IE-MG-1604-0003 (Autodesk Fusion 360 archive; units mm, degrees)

design "IS-MG-1604-0004" references "LED", "SFP SLOT", "Pluggable Terminal Block", "USB Type C Port (SMD Type) (1)", "Digitus_DN-651107_LAN-Switch x2", "8 ports ethernet", "M2.4 Screw", "DIP Switch"
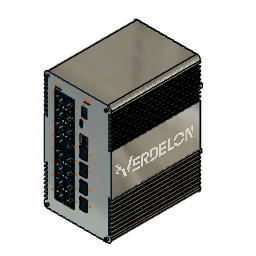
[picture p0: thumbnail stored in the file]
sketch "Sketch1" plane through (0, 0, 0) normal (0, 1, 0) x axis (1, 0, 0)
  line L1 (85, 0) -> (5, 0)
  line L2 (90, -155) -> (90, -5)
  line L3 (5, -160) -> (85, -160)
  line L4 (0, -5) -> (0, -155)
  arc A1 centre (85, -5) radius 5 clockwise from (85, 0) to (90, -5)
  arc A2 centre (5, -5) radius 5 clockwise from (0, -5) to (5, 0)
  arc A3 centre (85, -155) radius 5 clockwise from (90, -155) to (85, -160)
  arc A4 centre (5, -155) radius 5 clockwise from (5, -160) to (0, -155)
  point P1 (0, 0)
  point P2 (0, 0)
  point P3 (90, 0)
  point P4 (0, -160)
  horizontal L1
  vertical L2
  horizontal L3
  vertical L4
  coincident P1 P2
  coincident P3 L1
  coincident P3 L2
  tangent L1 A1
  tangent L2 A1
  coincident P2 L1
  coincident P2 L4
  tangent L1 A2
  tangent L4 A2
  equal A1 A2
  tangent L2 A3
  tangent L3 A3
  equal A1 A3
  coincident P4 L3
  coincident P4 L4
  tangent L3 A4
  tangent L4 A4
  equal A1 A4
  dimension "d1" distance P2 P4 = 160
  dimension "d2" distance P2 P3 = 90
  dimension "d3" radius A1 = 5
extrude "Extrude1" new body sketch "Sketch1" along normal blind 120
sketch "Sketch2" plane through (0, 0, 0) normal (0, -1, 0) x axis (1, 0, 0)
  line L1 (85, 0) -> (5, 0)
  line L2 (90, 155) -> (90, 5)
  line L3 (5, 160) -> (85, 160)
  line L4 (45, 80) -> (45, 160)
  line L5 (45, 80) -> (0, 80)
  line L6 (3.4641, 53) -> (0, 51)
  line L7 (3.4641, 50) -> (0, 48)
  line L8 (3.4641, 53) -> (3.4641, 50)
  line L9 (0, 51) -> (0, 48)
  line L10 (3.4641, 45) -> (0, 43)
  line L11 (0, 46) -> (0, 43)
  line L12 (3.4641, 48) -> (3.4641, 45)
  line L13 (3.4641, 48) -> (0, 46)
  line L14 (3.4641, 40) -> (0, 38)
  line L15 (0, 41) -> (0, 38)
  line L16 (3.4641, 43) -> (3.4641, 40)
  line L17 (3.4641, 43) -> (0, 41)
  line L18 (3.4641, 35) -> (0, 33)
  line L19 (0, 36) -> (0, 33)
  line L20 (3.4641, 38) -> (3.4641, 35)
  line L21 (3.4641, 38) -> (0, 36)
  line L22 (3.4641, 30) -> (0, 28)
  line L23 (0, 31) -> (0, 28)
  line L24 (3.4641, 33) -> (3.4641, 30)
  line L25 (3.4641, 33) -> (0, 31)
  line L26 (3.4641, 25) -> (0, 23)
  line L27 (0, 26) -> (0, 23)
  line L28 (3.4641, 28) -> (3.4641, 25)
  line L29 (3.4641, 28) -> (0, 26)
  line L30 (3.4641, 20) -> (0, 18)
  line L31 (0, 21) -> (0, 18)
  line L32 (3.4641, 23) -> (3.4641, 20)
  line L33 (3.4641, 23) -> (0, 21)
  line L34 (3.4641, 15) -> (0, 13)
  line L35 (0, 16) -> (0, 13)
  line L36 (3.4641, 18) -> (3.4641, 15)
  line L37 (3.4641, 18) -> (0, 16)
  line L38 (3.4641, 10) -> (0, 8)
  line L39 (0, 11) -> (0, 8)
  line L40 (3.4641, 13) -> (3.4641, 10)
  line L41 (3.4641, 13) -> (0, 11)
  line L42 (0, 129) -> (0, 132)
  line L43 (0, 149) -> (0, 152)
  line L44 (0, 109) -> (0, 112)
  line L45 (3.4641, 115) -> (0, 117)
  line L46 (3.4641, 112) -> (0, 114)
  line L47 (0, 119) -> (0, 122)
  line L48 (3.4641, 137) -> (3.4641, 140)
  line L49 (3.4641, 150) -> (0, 152)
  line L50 (3.4641, 142) -> (0, 144)
  line L51 (3.4641, 127) -> (0, 129)
  line L52 (0, 114) -> (0, 117)
  line L53 (3.4641, 122) -> (3.4641, 125)
  line L54 (3.4641, 142) -> (3.4641, 145)
  line L55 (3.4641, 135) -> (0, 137)
  line L56 (3.4641, 110) -> (0, 112)
  line L57 (3.4641, 132) -> (0, 134)
  line L58 (3.4641, 117) -> (0, 119)
  line L59 (0, 134) -> (0, 137)
  line L60 (3.4641, 117) -> (3.4641, 120)
  line L61 (3.4641, 130) -> (0, 132)
  line L62 (0, 144) -> (0, 147)
  line L63 (3.4641, 147) -> (0, 149)
  line L64 (3.4641, 147) -> (3.4641, 150)
  line L65 (3.4641, 122) -> (0, 124)
  line L66 (0, 124) -> (0, 127)
  line L67 (3.4641, 125) -> (0, 127)
  line L68 (3.4641, 107) -> (0, 109)
  line L69 (3.4641, 107) -> (3.4641, 110)
  line L70 (3.4641, 140) -> (0, 142)
  line L71 (3.4641, 145) -> (0, 147)
  line L72 (3.4641, 112) -> (3.4641, 115)
  line L73 (3.4641, 137) -> (0, 139)
  line L74 (0, 139) -> (0, 142)
  line L75 (3.4641, 132) -> (3.4641, 135)
  line L76 (3.4641, 120) -> (0, 122)
  line L77 (3.4641, 127) -> (3.4641, 130)
  line L78 (86.5359, 135) -> (90, 137)
  line L79 (90, 144) -> (90, 147)
  line L80 (90, 149) -> (90, 152)
  line L81 (90, 124) -> (90, 127)
  line L82 (86.5359, 120) -> (90, 122)
  line L83 (86.5359, 107) -> (90, 109)
  line L84 (86.5359, 117) -> (90, 119)
  line L85 (86.5359, 137) -> (90, 139)
  line L86 (86.5359, 122) -> (90, 124)
  line L87 (86.5359, 117) -> (86.5359, 120)
  line L88 (90, 114) -> (90, 117)
  line L89 (86.5359, 127) -> (86.5359, 130)
  line L90 (86.5359, 115) -> (90, 117)
  line L91 (86.5359, 130) -> (90, 132)
  line L92 (86.5359, 147) -> (86.5359, 150)
  line L93 (86.5359, 142) -> (86.5359, 145)
  line L94 (86.5359, 142) -> (90, 144)
  line L95 (90, 109) -> (90, 112)
  line L96 (90, 134) -> (90, 137)
  line L97 (86.5359, 107) -> (86.5359, 110)
  line L98 (86.5359, 132) -> (86.5359, 135)
  line L99 (86.5359, 112) -> (86.5359, 115)
  line L100 (86.5359, 137) -> (86.5359, 140)
  line L101 (86.5359, 110) -> (90, 112)
  line L102 (86.5359, 132) -> (90, 134)
  line L103 (86.5359, 145) -> (90, 147)
  line L104 (86.5359, 150) -> (90, 152)
  line L105 (90, 129) -> (90, 132)
  line L106 (86.5359, 112) -> (90, 114)
  line L107 (86.5359, 147) -> (90, 149)
  line L108 (90, 119) -> (90, 122)
  line L109 (86.5359, 127) -> (90, 129)
  line L110 (86.5359, 125) -> (90, 127)
  line L111 (86.5359, 122) -> (86.5359, 125)
  line L112 (90, 139) -> (90, 142)
  line L113 (86.5359, 140) -> (90, 142)
  line L114 (86.5359, 48) -> (86.5359, 45)
  line L115 (90, 46) -> (90, 43)
  line L116 (90, 36) -> (90, 33)
  line L117 (90, 41) -> (90, 38)
  line L118 (86.5359, 15) -> (90, 13)
  line L119 (90, 21) -> (90, 18)
  line L120 (86.5359, 53) -> (90, 51)
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  point P14 (45, 160)
  point P17 (0, 51)
  point P56 (0, 109)
  point P18 (3.4641, 53)
  point P88 (3.4641, 107)
  point P19 (0, 48)
  point P54 (0, 112)
  point P20 (3.4641, 50)
  point P55 (3.4641, 110)
  point P21 (0, 43)
  point P62 (0, 117)
  point P22 (3.4641, 45)
  point P61 (3.4641, 115)
  point P23 (0, 46)
  point P59 (0, 114)
  point P24 (3.4641, 48)
  point P60 (3.4641, 112)
  point P25 (0, 38)
  point P58 (0, 122)
  point P26 (3.4641, 40)
  point P53 (3.4641, 120)
  point P27 (0, 41)
  point P57 (0, 119)
  point P28 (3.4641, 43)
  point P85 (3.4641, 117)
  point P29 (0, 33)
  point P81 (0, 127)
  point P30 (3.4641, 35)
  point P78 (3.4641, 125)
  point P31 (0, 36)
  point P80 (0, 124)
  point P32 (3.4641, 38)
  point P86 (3.4641, 122)
  point P33 (0, 28)
  point P79 (0, 132)
  point P34 (3.4641, 30)
  point P87 (3.4641, 130)
  point P35 (0, 31)
  point P82 (0, 129)
  point P36 (3.4641, 33)
  point P75 (3.4641, 127)
  point P37 (0, 23)
  point P83 (0, 137)
  point P38 (3.4641, 25)
  point P77 (3.4641, 135)
  point P39 (0, 26)
  point P84 (0, 134)
  point P40 (3.4641, 28)
  point P76 (3.4641, 132)
  point P41 (0, 18)
  point P70 (0, 142)
  point P42 (3.4641, 20)
  point P68 (3.4641, 140)
  point P43 (0, 21)
  point P74 (0, 139)
  point P44 (3.4641, 23)
  point P71 (3.4641, 137)
  point P45 (0, 13)
  point P63 (0, 147)
  point P46 (3.4641, 15)
  point P67 (3.4641, 145)
  point P47 (0, 16)
  point P73 (0, 144)
  point P48 (3.4641, 18)
  point P65 (3.4641, 142)
  point P49 (0, 8)
  point P69 (0, 152)
  point P50 (3.4641, 10)
  point P64 (3.4641, 150)
  point P51 (0, 11)
  point P66 (0, 149)
  point P52 (3.4641, 13)
  point P72 (3.4641, 147)
  point P11 (5, 160)
  point P163 (85, 160)
  point P12 (0, 155)
  point P120 (90, 155)
  point P127 (90, 51)
  point P130 (86.5359, 53)
  point P128 (90, 48)
  point P140 (86.5359, 50)
  point P132 (90, 43)
  point P159 (86.5359, 45)
  point P153 (90, 46)
  point P150 (86.5359, 48)
  point P152 (90, 38)
  point P146 (86.5359, 40)
  point P135 (90, 41)
  point P138 (86.5359, 43)
  point P133 (90, 33)
  point P134 (86.5359, 35)
  point P129 (90, 36)
  point P131 (86.5359, 38)
  point P143 (90, 28)
  point P144 (86.5359, 30)
  point P142 (90, 31)
  point P147 (86.5359, 33)
  point P149 (90, 23)
  point P160 (86.5359, 25)
  point P162 (90, 26)
  point P161 (86.5359, 28)
  point P155 (90, 18)
  point P148 (86.5359, 20)
  point P154 (90, 21)
  point P151 (86.5359, 23)
  point P145 (90, 13)
  point P141 (86.5359, 15)
  point P157 (90, 16)
  point P156 (86.5359, 18)
  point P158 (90, 8)
  point P136 (86.5359, 10)
  point P137 (90, 11)
  point P139 (86.5359, 13)
  point P91 (86.5359, 120)
  point P93 (90, 112)
  point P119 (86.5359, 110)
  point P115 (90, 109)
  point P116 (90, 119)
  point P118 (90, 122)
  point P123 (90, 114)
  point P108 (86.5359, 112)
  point P97 (86.5359, 115)
  point P110 (90, 117)
  point P99 (90, 147)
  point P111 (86.5359, 150)
  point P104 (86.5359, 142)
  point P105 (90, 149)
  point P101 (86.5359, 145)
  point P103 (86.5359, 140)
  point P95 (90, 152)
  point P98 (90, 142)
  point P96 (86.5359, 137)
  point P100 (86.5359, 147)
  point P117 (90, 144)
  point P126 (90, 139)
  point P106 (86.5359, 127)
  point P107 (86.5359, 132)
  point P114 (86.5359, 135)
  point P102 (86.5359, 125)
  point P121 (90, 132)
  point P113 (90, 124)
  point P124 (90, 127)
  point P112 (90, 129)
  point P125 (90, 137)
  point P89 (90, 134)
  point P122 (86.5359, 117)
  point P94 (86.5359, 122)
  point P90 (86.5359, 130)
  point P92 (86.5359, 107)
  midpoint L3 P14
  perpendicular L3 L4
  perpendicular L4 L5
  symmetric L5 P17 P56
  symmetric L5 P18 P88
  symmetric L5 P19 P54
  symmetric L5 P20 P55
  symmetric L5 P21 P62
  symmetric L5 P22 P61
  symmetric L5 P23 P59
  symmetric L5 P24 P60
  symmetric L5 P25 P58
  symmetric L5 P26 P53
  symmetric L5 P27 P57
  symmetric L5 P28 P85
  symmetric L5 P29 P81
  symmetric L5 P30 P78
  symmetric L5 P31 P80
  symmetric L5 P32 P86
  symmetric L5 P33 P79
  symmetric L5 P34 P87
  symmetric L5 P35 P82
  symmetric L5 P36 P75
  symmetric L5 P37 P83
  symmetric L5 P38 P77
  symmetric L5 P39 P84
  symmetric L5 P40 P76
  symmetric L5 P41 P70
  symmetric L5 P42 P68
  symmetric L5 P43 P74
  symmetric L5 P44 P71
  symmetric L5 P45 P63
  symmetric L5 P46 P67
  symmetric L5 P47 P73
  symmetric L5 P48 P65
  symmetric L5 P49 P69
  symmetric L5 P50 P64
  symmetric L5 P51 P66
  symmetric L5 P52 P72
  symmetric P11 L4 P163
  symmetric P12 L4 P120
  symmetric L4 P17 P127
  symmetric L4 P18 P130
  symmetric L4 P19 P128
  symmetric L4 P20 P140
  symmetric L4 P21 P132
  symmetric L4 P22 P159
  symmetric L4 P23 P153
  symmetric L4 P24 P150
  symmetric L4 P25 P152
  symmetric L4 P26 P146
  symmetric L4 P27 P135
  symmetric L4 P28 P138
  symmetric L4 P29 P133
  symmetric L4 P30 P134
  symmetric L4 P31 P129
  symmetric L4 P32 P131
  symmetric L4 P33 P143
  symmetric L4 P34 P144
  symmetric L4 P35 P142
  symmetric L4 P36 P147
  symmetric L4 P37 P149
  symmetric L4 P38 P160
  symmetric L4 P39 P162
  symmetric L4 P40 P161
  symmetric L4 P41 P155
  symmetric L4 P42 P148
  symmetric L4 P43 P154
  symmetric L4 P44 P151
  symmetric L4 P45 P145
  symmetric L4 P46 P141
  symmetric L4 P47 P157
  symmetric L4 P48 P156
  symmetric L4 P49 P158
  symmetric L4 P50 P136
  symmetric L4 P51 P137
  symmetric L4 P52 P139
  symmetric L4 P53 P91
  symmetric L4 P54 P93
  symmetric L4 P55 P119
  symmetric L4 P56 P115
  symmetric L4 P57 P116
  symmetric L4 P58 P118
  symmetric L4 P59 P123
  symmetric L4 P60 P108
  symmetric L4 P61 P97
  symmetric L4 P62 P110
  symmetric L4 P63 P99
  symmetric L4 P64 P111
  symmetric L4 P65 P104
  symmetric L4 P66 P105
  symmetric L4 P67 P101
  symmetric L4 P68 P103
  symmetric L4 P69 P95
  symmetric L4 P70 P98
  symmetric L4 P71 P96
  symmetric L4 P72 P100
  symmetric L4 P73 P117
  symmetric L4 P74 P126
  symmetric L4 P75 P106
  symmetric L4 P76 P107
  symmetric L4 P77 P114
  symmetric L4 P78 P102
  symmetric L4 P79 P121
  symmetric L4 P80 P113
  symmetric L4 P81 P124
  symmetric L4 P82 P112
  symmetric L4 P83 P125
  symmetric L4 P84 P89
  symmetric L4 P85 P122
  symmetric L4 P86 P94
  symmetric L4 P87 P90
  symmetric L4 P88 P92
  dimension "d6" distance P17 P18 = 2
  dimension "d16" distance L5 P18 = 27
  dimension "d10" R-Pattern1-uDistance = 0
  dimension "d11" R-Pattern1-vDistance = -3
  dimension "d14" R-Pattern2-uDistance = 0
  dimension "d15" R-Pattern2-vDistance = -40
extrude "Extrude3" cut sketch "Sketch2" against normal blind 120
sketch "Sketch3" plane through (0, 0, 0) normal (0, -1, 0) x axis (1, 0, 0)
  line L1 (0, 18) -> (3.4641, 20)
  line L2 (0, 16) -> (0, 18)
  line L3 (3.4641, 18) -> (0, 16)
  line L4 (3.4641, 15) -> (3.4641, 18)
  line L5 (0, 13) -> (3.4641, 15)
  line L6 (0, 11) -> (0, 13)
  line L7 (3.4641, 13) -> (0, 11)
  line L8 (3.4641, 10) -> (3.4641, 13)
  line L9 (0, 8) -> (3.4641, 10)
  line L10 (0, 5) -> (0, 8)
  line L11 (85, 0) -> (5, 0)
  line L12 (90, 8) -> (90, 5)
  line L13 (86.5359, 10) -> (90, 8)
  line L14 (86.5359, 13) -> (86.5359, 10)
  line L15 (90, 11) -> (86.5359, 13)
  line L16 (90, 13) -> (90, 11)
  line L17 (86.5359, 15) -> (90, 13)
  line L18 (86.5359, 18) -> (86.5359, 15)
  line L19 (90, 16) -> (86.5359, 18)
  line L20 (90, 18) -> (90, 16)
  line L21 (86.5359, 20) -> (90, 18)
  line L22 (86.5359, 23) -> (86.5359, 20)
  line L23 (90, 21) -> (86.5359, 23)
  line L24 (90, 23) -> (90, 21)
  line L25 (86.5359, 25) -> (90, 23)
  line L26 (86.5359, 28) -> (86.5359, 25)
  line L27 (90, 26) -> (86.5359, 28)
  line L28 (90, 28) -> (90, 26)
  line L29 (86.5359, 30) -> (90, 28)
  line L30 (86.5359, 33) -> (86.5359, 30)
  line L31 (90, 31) -> (86.5359, 33)
  line L32 (90, 33) -> (90, 31)
  line L33 (86.5359, 35) -> (90, 33)
  line L34 (86.5359, 38) -> (86.5359, 35)
  line L35 (90, 36) -> (86.5359, 38)
  line L36 (90, 38) -> (90, 36)
  line L37 (86.5359, 40) -> (90, 38)
  line L38 (86.5359, 43) -> (86.5359, 40)
  line L39 (90, 41) -> (86.5359, 43)
  line L40 (90, 43) -> (90, 41)
  line L41 (86.5359, 45) -> (90, 43)
  line L42 (86.5359, 48) -> (86.5359, 45)
  line L43 (90, 46) -> (86.5359, 48)
  line L44 (90, 48) -> (90, 46)
  line L45 (86.5359, 50) -> (90, 48)
  line L46 (86.5359, 53) -> (86.5359, 50)
  line L47 (90, 51) -> (86.5359, 53)
  line L48 (90, 109) -> (90, 51)
  line L49 (86.5359, 107) -> (90, 109)
  line L50 (86.5359, 110) -> (86.5359, 107)
  line L51 (90, 112) -> (86.5359, 110)
  line L52 (90, 114) -> (90, 112)
  line L53 (86.5359, 112) -> (90, 114)
  line L54 (86.5359, 115) -> (86.5359, 112)
  line L55 (90, 117) -> (86.5359, 115)
  line L56 (90, 119) -> (90, 117)
  line L57 (86.5359, 117) -> (90, 119)
  line L58 (86.5359, 120) -> (86.5359, 117)
  line L59 (90, 122) -> (86.5359, 120)
  line L60 (90, 124) -> (90, 122)
  line L61 (86.5359, 122) -> (90, 124)
  line L62 (86.5359, 125) -> (86.5359, 122)
  line L63 (90, 127) -> (86.5359, 125)
  line L64 (90, 129) -> (90, 127)
  line L65 (86.5359, 127) -> (90, 129)
  line L66 (86.5359, 130) -> (86.5359, 127)
  line L67 (90, 132) -> (86.5359, 130)
  line L68 (90, 134) -> (90, 132)
  line L69 (86.5359, 132) -> (90, 134)
  line L70 (86.5359, 135) -> (86.5359, 132)
  line L71 (90, 137) -> (86.5359, 135)
  line L72 (90, 139) -> (90, 137)
  line L73 (86.5359, 137) -> (90, 139)
  line L74 (86.5359, 140) -> (86.5359, 137)
  line L75 (90, 142) -> (86.5359, 140)
  line L76 (90, 144) -> (90, 142)
  line L77 (86.5359, 142) -> (90, 144)
  line L78 (86.5359, 145) -> (86.5359, 142)
  line L79 (90, 147) -> (86.5359, 145)
  line L80 (90, 149) -> (90, 147)
  line L81 (86.5359, 147) -> (90, 149)
  line L82 (86.5359, 150) -> (86.5359, 147)
  line L83 (90, 152) -> (86.5359, 150)
  line L84 (90, 155) -> (90, 152)
  line L85 (5, 160) -> (85, 160)
  line L86 (0, 152) -> (0, 155)
  line L87 (3.4641, 150) -> (0, 152)
  line L88 (3.4641, 147) -> (3.4641, 150)
  line L89 (0, 149) -> (3.4641, 147)
  line L90 (0, 147) -> (0, 149)
  line L91 (3.4641, 145) -> (0, 147)
  line L92 (3.4641, 142) -> (3.4641, 145)
  line L93 (0, 144) -> (3.4641, 142)
  line L94 (0, 142) -> (0, 144)
  line L95 (3.4641, 140) -> (0, 142)
  line L96 (3.4641, 137) -> (3.4641, 140)
  line L97 (0, 139) -> (3.4641, 137)
  line L98 (0, 137) -> (0, 139)
  line L99 (3.4641, 135) -> (0, 137)
  line L100 (3.4641, 132) -> (3.4641, 135)
  line L101 (0, 134) -> (3.4641, 132)
  line L102 (0, 132) -> (0, 134)
  line L103 (3.4641, 130) -> (0, 132)
  line L104 (3.4641, 127) -> (3.4641, 130)
  line L105 (0, 129) -> (3.4641, 127)
  line L106 (0, 127) -> (0, 129)
  line L107 (3.4641, 125) -> (0, 127)
  line L108 (3.4641, 122) -> (3.4641, 125)
  line L109 (0, 124) -> (3.4641, 122)
  line L110 (0, 122) -> (0, 124)
  line L111 (3.4641, 120) -> (0, 122)
  line L112 (3.4641, 117) -> (3.4641, 120)
  line L113 (0, 119) -> (3.4641, 117)
  line L114 (0, 117) -> (0, 119)
  line L115 (3.4641, 115) -> (0, 117)
  line L116 (3.4641, 112) -> (3.4641, 115)
  line L117 (0, 114) -> (3.4641, 112)
  line L118 (0, 112) -> (0, 114)
  line L119 (3.4641, 110) -> (0, 112)
  line L120 (3.4641, 107) -> (3.4641, 110)
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  point P158 (45, 160)
  point P173 (48, 108.7134)
  point P256 (48, 108.7134)
  point P172 (58, 108.7134)
  point P255 (58, 108.7134)
  point P254 (58, 108.7134)
  point P257 (48, 108.7134)
  point P171 (58, 97.7134)
  point P252 (58, 97.7134)
  point P253 (58, 97.7134)
  point P161 (14.2, 143.8)
  point P164 (14.2, 16.2)
  point P162 (40, 143.8)
  point P168 (57.7, 21.2)
  point P169 (57.7, 35.7)
  point P170 (48, 35.7)
  point P175 (57.21, 141.6534)
  point P176 (57.21, 129.7834)
  point P174 (50.21, 141.6534)
  point P178 (52.01, 143.6534)
  point P183 (54.01, 148.6534)
  midpoint L85 P158
  coincident P173 P256
  coincident P172 P255
  coincident P172 P254
  coincident P173 P257
  coincident P171 P252
  coincident P171 P253
  dimension "d21" distance P161 P164 = 127.6
  dimension "d22" distance P161 P162 = 25.8
  dimension "d23" distance = 5
  dimension "d24" distance P168 P169 = 14.5
  dimension "d25" distance P169 P170 = 9.7
  dimension "d30" distance = 5
  dimension "d31" distance = 8
  dimension "d32" distance P171 P172 = 11
  dimension "d33" distance P172 P173 = 10
  dimension "d34" distance = 2
  dimension "d35" distance = 8.94
  dimension "d36" distance = 3.21
  dimension "d37" distance = 8
  dimension "d38" distance P175 P176 = 11.87
  dimension "d39" distance P174 P175 = 7
  dimension "d42" distance = 1
  dimension "d43" diameter = 1
  dimension "d44" distance = 2
  dimension "d45" distance = 1.8
  dimension "d46" diameter = 1.5
  dimension "d47" distance = 3
  dimension "d48" distance = 1.5
  dimension "d53" diameter = 1.5
  dimension "d54" distance P178 P183 = 5
  dimension "d55" distance P178 P183 = 2
  dimension "d60" diameter = 1.7
  dimension "d69" radius = 1.25
  dimension "d77" radius = 0.75
  dimension "d82" distance = 5.5
  dimension "d83" distance = 5.5
  dimension "d169" distance = 14.5
  dimension "d51" R-Pattern2-uDistance = 6
  dimension "d52" R-Pattern2-vDistance = 0
  dimension "d58" R-Pattern3-uDistance = 6
  dimension "d59" R-Pattern3-vDistance = 0
  dimension "d63" R-Pattern4-uDistance = 80
  dimension "d64" R-Pattern4-vDistance = 0
  dimension "d67" R-Pattern5-uDistance = 0
  dimension "d68" R-Pattern5-vDistance = -150
extrude "Extrude4" cut sketch "Sketch3" against normal blind 10
shell "Shell1" innerThickness 1
component_insert "Component Insert18"
position "Position1"
rectangular_pattern "00000000-0000-0000-0000-000000000000" uSpaceDistance 63.8 vSpaceDistance 0
component_insert "Component Insert2"
position "Position2"
rectangular_pattern "00000000-0000-0000-0000-000000000000" uSpaceDistance -60 vSpaceDistance 0
component_insert "Component Insert4"
position "Position3"
position "Position4"
position "Position5"
component_insert "Component Insert5"
position "Position6"
position "Position7"
position "Position8"
component_insert "Component Insert8"
position "Position9"
position "Position10"
position "Position11"
component_insert "Component Insert12"
joint "Assemble2" alignAngle 0 alignOffsetX 0 alignOffsetY 0 alignOffsetZ 2.2
rectangular_pattern "00000000-0000-0000-0000-000000000000" uSpaceDistance 6 vSpaceDistance 0
component_insert "Component Insert13"
joint "Assemble3" alignAngle 0 alignOffsetX 0 alignOffsetY 0 alignOffsetZ 2.2
rectangular_pattern "00000000-0000-0000-0000-000000000000" uSpaceDistance 6 vSpaceDistance 0
sketch "Sketch4" plane through (0, 0, 0) normal (0, -1, 0) x axis (1, 0, 0)
  line L1 (56.95, 35.7) -> (48.75, 35.7)
  line L2 (57.7, 21.95) -> (57.7, 34.95)
  line L3 (48.75, 21.2) -> (56.95, 21.2)
  line L4 (48, 34.95) -> (48, 21.95)
  line L5 (48, 97.7134) -> (58, 97.7134)
  line L6 (48, 108.7134) -> (48, 97.7134)
  line L7 (58, 108.7134) -> (48, 108.7134)
  line L8 (58, 97.7134) -> (58, 108.7134)
  line L9 (57.21, 129.7834) -> (57.21, 141.6534)
  line L10 (50.21, 129.7834) -> (57.21, 129.7834)
  line L11 (50.21, 141.6534) -> (50.21, 129.7834)
  line L12 (57.21, 141.6534) -> (50.21, 141.6534)
  line L13 (49.25, 116.7134) -> (49.96, 116.7134)
  line L14 (48, 124.4034) -> (48, 117.9634)
  line L15 (49.96, 125.6534) -> (49.25, 125.6534)
  line L16 (51.21, 117.9634) -> (51.21, 124.4034)
  line L17 (48, 54.95) -> (48, 41.95)
  line L18 (56.95, 55.7) -> (48.75, 55.7)
  line L19 (57.7, 41.95) -> (57.7, 54.95)
  line L20 (48.75, 41.2) -> (56.95, 41.2)
  line L21 (48, 94.9634) -> (48, 81.9504)
  line L22 (56.9494, 95.7134) -> (48.75, 95.7134)
  line L23 (57.6994, 81.9504) -> (57.6994, 94.9634)
  line L24 (48.75, 81.2004) -> (56.9494, 81.2004)
  line L25 (40, 16.2) -> (40, 143.8)
  line L26 (14.2, 16.2) -> (40, 16.2)
  line L27 (14.2, 143.8) -> (14.2, 16.2)
  line L28 (40, 143.8) -> (14.2, 143.8)
  line L29 (48, 74.95) -> (48, 61.95)
  line L30 (56.9494, 75.7) -> (48.75, 75.7)
  line L31 (57.6994, 61.95) -> (57.6994, 74.95)
  line L32 (48.75, 61.2) -> (56.9494, 61.2)
  line L33 (0, 18) -> (3.4641, 20)
  line L34 (0, 16) -> (0, 18)
  line L35 (3.4641, 18) -> (0, 16)
  line L36 (3.4641, 15) -> (3.4641, 18)
  line L37 (0, 13) -> (3.4641, 15)
  line L38 (0, 11) -> (0, 13)
  line L39 (3.4641, 13) -> (0, 11)
  line L40 (3.4641, 10) -> (3.4641, 13)
  line L41 (0, 8) -> (3.4641, 10)
  line L42 (0, 5) -> (0, 8)
  line L43 (85, 0) -> (5, 0)
  line L44 (90, 8) -> (90, 5)
  line L45 (86.5359, 10) -> (90, 8)
  line L46 (86.5359, 13) -> (86.5359, 10)
  line L47 (90, 11) -> (86.5359, 13)
  line L48 (90, 13) -> (90, 11)
  line L49 (86.5359, 15) -> (90, 13)
  line L50 (86.5359, 18) -> (86.5359, 15)
  line L51 (90, 16) -> (86.5359, 18)
  line L52 (90, 18) -> (90, 16)
  line L53 (86.5359, 20) -> (90, 18)
  line L54 (86.5359, 23) -> (86.5359, 20)
  line L55 (90, 21) -> (86.5359, 23)
  line L56 (90, 23) -> (90, 21)
  line L57 (86.5359, 25) -> (90, 23)
  line L58 (86.5359, 28) -> (86.5359, 25)
  line L59 (90, 26) -> (86.5359, 28)
  line L60 (90, 28) -> (90, 26)
  line L61 (86.5359, 30) -> (90, 28)
  line L62 (86.5359, 33) -> (86.5359, 30)
  line L63 (90, 31) -> (86.5359, 33)
  line L64 (90, 33) -> (90, 31)
  line L65 (86.5359, 35) -> (90, 33)
  line L66 (86.5359, 38) -> (86.5359, 35)
  line L67 (90, 36) -> (86.5359, 38)
  line L68 (90, 38) -> (90, 36)
  line L69 (86.5359, 40) -> (90, 38)
  line L70 (86.5359, 43) -> (86.5359, 40)
  line L71 (90, 41) -> (86.5359, 43)
  line L72 (90, 43) -> (90, 41)
  line L73 (86.5359, 45) -> (90, 43)
  line L74 (86.5359, 48) -> (86.5359, 45)
  line L75 (90, 46) -> (86.5359, 48)
  line L76 (90, 48) -> (90, 46)
  line L77 (86.5359, 50) -> (90, 48)
  line L78 (86.5359, 53) -> (86.5359, 50)
  line L79 (90, 51) -> (86.5359, 53)
  line L80 (90, 109) -> (90, 51)
  line L81 (86.5359, 107) -> (90, 109)
  line L82 (86.5359, 110) -> (86.5359, 107)
  line L83 (90, 112) -> (86.5359, 110)
  line L84 (90, 114) -> (90, 112)
  line L85 (86.5359, 112) -> (90, 114)
  line L86 (86.5359, 115) -> (86.5359, 112)
  line L87 (90, 117) -> (86.5359, 115)
  line L88 (90, 119) -> (90, 117)
  line L89 (86.5359, 117) -> (90, 119)
  line L90 (86.5359, 120) -> (86.5359, 117)
  line L91 (90, 122) -> (86.5359, 120)
  line L92 (90, 124) -> (90, 122)
  line L93 (86.5359, 122) -> (90, 124)
  line L94 (86.5359, 125) -> (86.5359, 122)
  line L95 (90, 127) -> (86.5359, 125)
  line L96 (90, 129) -> (90, 127)
  line L97 (86.5359, 127) -> (90, 129)
  line L98 (86.5359, 130) -> (86.5359, 127)
  line L99 (90, 132) -> (86.5359, 130)
  line L100 (90, 134) -> (90, 132)
  line L101 (86.5359, 132) -> (90, 134)
  line L102 (86.5359, 135) -> (86.5359, 132)
  line L103 (90, 137) -> (86.5359, 135)
  line L104 (90, 139) -> (90, 137)
  line L105 (86.5359, 137) -> (90, 139)
  line L106 (86.5359, 140) -> (86.5359, 137)
  line L107 (90, 142) -> (86.5359, 140)
  line L108 (90, 144) -> (90, 142)
  line L109 (86.5359, 142) -> (90, 144)
  line L110 (86.5359, 145) -> (86.5359, 142)
  line L111 (90, 147) -> (86.5359, 145)
  line L112 (90, 149) -> (90, 147)
  line L113 (86.5359, 147) -> (90, 149)
  line L114 (86.5359, 150) -> (86.5359, 147)
  line L115 (90, 152) -> (86.5359, 150)
  line L116 (90, 155) -> (90, 152)
  line L117 (5, 160) -> (85, 160)
  line L118 (0, 152) -> (0, 155)
  line L119 (3.4641, 150) -> (0, 152)
  line L120 (3.4641, 147) -> (3.4641, 150)
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  dimension "d120" Text1-Height = 2
  dimension "d121" Text2-Height = 2
  dimension "d122" Text3-Height = 2
  dimension "d123" Text4-Height = 2
  dimension "d124" Text5-Height = 2
  dimension "d125" Text6-Height = 2
  dimension "d126" Text7-Height = 2
  dimension "d127" Text8-Height = 2
  dimension "d128" Text9-Height = 2
  dimension "d129" Text10-Height = 2
  dimension "d130" Text11-Height = 2
  dimension "d131" Text12-Height = 2
  dimension "d132" Text13-Height = 2
  dimension "d133" Text14-Height = 2
  dimension "d134" Text15-Height = 2
  dimension "d135" Text16-Height = 2
  dimension "d136" Text17-Height = 2
  dimension "d137" Text18-Height = 2
  dimension "d138" Text19-Height = 2
  dimension "d139" Text20-Height = 2
  dimension "d140" Text21-Height = 1
  dimension "d141" Text22-Height = 1
  dimension "d142" Text23-Height = 1
  dimension "d144" Text24-Height = 1
  dimension "d145" Text25-Height = 1
  dimension "d146" Text26-Height = 1
  dimension "d147" Text27-Height = 1
  dimension "d148" Text28-Height = 1.5
component_insert "Component Insert16"
position "Position12"
component_insert "Component Insert17"
joint "Assemble4" alignAngle 90 alignOffsetX 0 alignOffsetY 0 alignOffsetZ -3.8
rectangular_pattern "00000000-0000-0000-0000-000000000000" uSpaceDistance -80 vSpaceDistance 0
rectangular_pattern "00000000-0000-0000-0000-000000000000" uSpaceDistance -150 vSpaceDistance 0
decal "Decal1"
decal "Decal2"
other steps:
joint_origin "JointOrigin3"
joint_origin "JointOrigin4"
joint_origin "JointOrigin5" sketch "Sketch4"

design "Digitus_DN-651107_LAN-Switch x2"
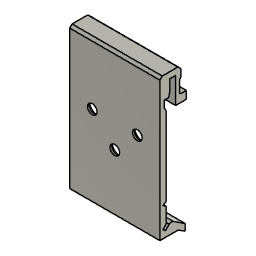
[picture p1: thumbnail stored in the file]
description: STEP AP214
part number: Digitus_DN-651107_LAN-Switch x2

design "Pluggable Terminal Block"
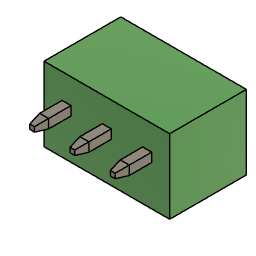
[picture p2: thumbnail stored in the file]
description: STEP AP214
part number: Pluggable Terminal Block

design "8 ports ethernet"
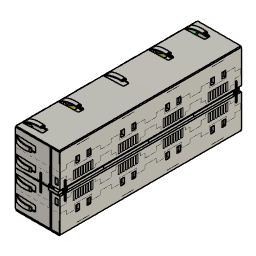
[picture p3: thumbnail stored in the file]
description: STEP AP214
part number: 8 ports ethernet

design "USB Type C Port (SMD Type) (1)"
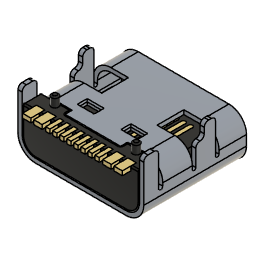
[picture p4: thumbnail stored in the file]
description: STEP AP214
part number: USB Type C Port (SMD Type) (1)

design "DIP Switch"
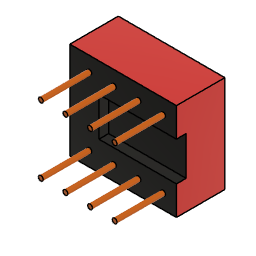
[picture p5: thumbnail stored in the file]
description: STEP AP214
part number: DIP Switch

design "LED"
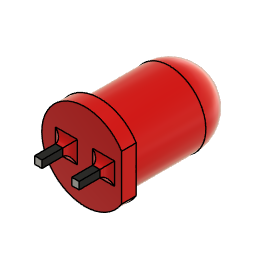
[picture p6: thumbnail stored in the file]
description: STEP AP214
part number: LED

design "M2.4 Screw"
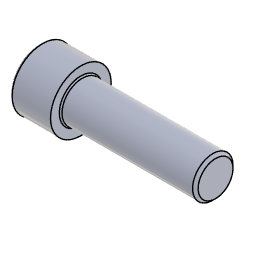
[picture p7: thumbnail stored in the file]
description: STEP AP214
part number: M2.4 Screw

design "SFP SLOT"
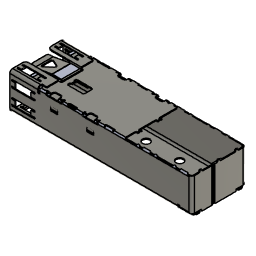
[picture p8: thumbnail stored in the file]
description: STEP AP214
part number: SFP SLOT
